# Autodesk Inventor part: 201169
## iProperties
Created: 2007-10
Part Number: 201169
Document SubType Name: Modeling
Designer: TH
Density: 8.08 g/cm^3
Mass: 849.269 g
Surface Area: 958.493 cm^2
Volume: 105.108 cm^3
Material: Stainless Steel
Description: BOTTOM RAIL
Component Category: Lower Component
Author: TH
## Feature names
1. Extrusion1
2. Extrusion2
3. Fillet1
4. Fillet2
5. Extrusion3
6. Extrusion4
7. Rectangular Pattern1
8. Hole1
9. Hole2
